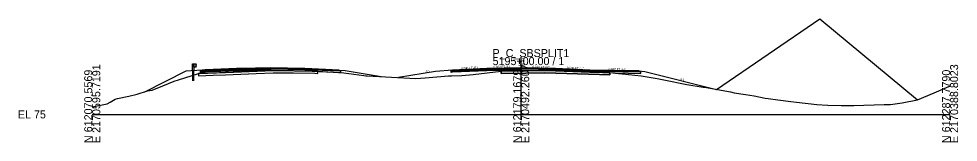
# Model space of a CAD drawing. Extents: x -26 to 1303, y -3010 to 12033.
# Drawn here: x -25.7 to 302.8, y 11990.3 to 12033.3 of the extents above; entities that cross this region are included whole.
import ezdxf

# ---------------------------------------------------------------- set-up
doc = ezdxf.new("R2010")
doc.units = 0
for name, color, linetype in [('RD_GPK_XS_Cell', 7, 'Continuous'), ('RD_PD_Final_TrvlWay', 7, 'Continuous'), ('RD_Sketch10', 7, 'Continuous'), ('RD_XS_Base', 7, 'Continuous'), ('RD_XS_ExGround', 7, 'Continuous'), ('RD_XS_ExPaveRet', 7, 'Continuous'), ('RD_XS_GR', 7, 'Continuous'), ('RD_XS_Greenside', 7, 'Continuous'), ('RD_XS_Pave', 7, 'Continuous'), ('RD_XS_PaveOvlay_CP', 7, 'Continuous'), ('RD_XS_TieSlope', 7, 'Continuous'), ('RD_XS_TX_Elev_EX', 7, 'Continuous'), ('RD_XS_TX_Elev_PR', 7, 'Continuous'), ('RD_XS_TX_Slope', 7, 'Continuous')]:
    doc.layers.add(name, color=color, linetype=linetype)

msp = doc.modelspace()

# ---------------------------------------------------------------- linework, layer by layer
at = {"layer": 'RD_GPK_XS_Cell'}
for p, q in [((150, 12000), (150, 12020)), ((0, 12000), (150, 12000)), ((150, 12000), (300, 12000))]:
    msp.add_line(p, q, dxfattribs=at)
at = {"layer": 'RD_PD_Final_TrvlWay'}
msp.add_lwpolyline([(35.54, 12011.66), (35.54, 12015.26), (35.04, 12015.22), (35.04, 12011.66)], dxfattribs=at)
at = {"layer": 'RD_Sketch10'}
msp.add_lwpolyline([(218.34, 12008.73), (254.46, 12033.35), (288.57, 12005.04)], dxfattribs=at)
at = {"layer": 'RD_XS_Base'}
for p, q in [((37.89, 12014.7), (37.89, 12015.15)), ((37.89, 12015.15), (37.94, 12015.15)), ((37.89, 12014.65), (37.89, 12014.7)), ((37.94, 12014.65), (37.89, 12014.65)), ((37.94, 12015.15), (38.39, 12015.17)), ((38.39, 12014.67), (37.94, 12014.65)), ((38.39, 12015.17), (39.51, 12015.22)), ((39.51, 12014.72), (38.39, 12014.67)), ((39.51, 12015.22), (50.39, 12015.65)), ((50.39, 12015.15), (39.51, 12014.72)), ((50.39, 12015.65), (51.68, 12015.68)), ((51.68, 12015.18), (50.39, 12015.15)), ((51.68, 12015.68), (62.39, 12015.89)), ((62.39, 12015.39), (51.68, 12015.18)), ((62.39, 12015.91), (62.39, 12016.05)), ((62.39, 12016.05), (62.39, 12015.47)), ((62.39, 12015.89), (62.39, 12016.05)), ((62.39, 12016.05), (62.39, 12015.39)), ((62.39, 12015.89), (62.39, 12015.91)), ((62.39, 12015.89), (62.39, 12015.45)), ((62.39, 12015.89), (62.39, 12015.39)), ((74.39, 12015.65), (62.39, 12015.89)), ((62.39, 12015.89), (62.39, 12015.89)), ((62.39, 12015.47), (62.39, 12015.39)), ((62.39, 12015.45), (62.39, 12015.39)), ((62.39, 12015.39), (62.39, 12015.39)), ((62.39, 12015.39), (62.39, 12015.39)), ((62.39, 12015.39), (74.39, 12015.15)), ((86.39, 12015.17), (74.39, 12015.65)), ((74.39, 12015.15), (86.89, 12014.65)), ((76.39, 12015.57), (76.39, 12015.57)), ((76.39, 12015.07), (76.39, 12015.07)), ((86.89, 12015.15), (86.39, 12015.17)), ((86.39, 12015.17), (86.39, 12015.17)), ((86.89, 12014.65), (86.89, 12015.15)), ((86.89, 12015.15), (86.89, 12015.15)), ((86.89, 12014.65), (86.89, 12014.65)), ((86.89, 12014.65), (86.89, 12014.65)), ((125.5, 12015.16), (126, 12015.18)), ((125.5, 12014.66), (125.5, 12015.16)), ((125.5, 12015.16), (125.5, 12015.16)), ((126, 12014.68), (125.5, 12014.66)), ((125.5, 12014.66), (125.5, 12014.66)), ((125.5, 12014.66), (125.5, 12014.66)), ((126, 12015.18), (138, 12015.66)), ((126, 12015.18), (126, 12015.18)), ((138, 12015.16), (126, 12014.68)), ((126, 12014.68), (126, 12014.68)), ((136, 12015.58), (136, 12015.58)), ((136, 12015.08), (136, 12015.08)), ((138, 12015.66), (150, 12015.9)), ((150, 12015.4), (138, 12015.16)), ((150, 12015.9), (150, 12016.06)), ((150, 12016.06), (150, 12015.4)), ((150, 12015.9), (150, 12015.9)), ((162, 12015.66), (150, 12015.9)), ((150, 12015.9), (150, 12015.9)), ((150, 12015.9), (150, 12015.4)), ((150, 12015.4), (150, 12015.4)), ((150, 12015.4), (162, 12015.16)), ((150, 12015.4), (150, 12015.4)), ((174, 12015.18), (162, 12015.66)), ((162, 12015.66), (162, 12015.66)), ((162, 12015.16), (162, 12015.16)), ((162, 12015.16), (174, 12014.68)), ((191.3, 12014.83), (174, 12015.18)), ((174, 12015.18), (174, 12015.18)), ((174, 12014.68), (174, 12014.68)), ((174, 12014.68), (191.8, 12014.32)), ((191.8, 12014.82), (191.3, 12014.83)), ((191.3, 12014.83), (191.3, 12014.83)), ((191.8, 12014.32), (191.8, 12014.82)), ((191.8, 12014.82), (191.8, 12014.82)), ((191.8, 12014.32), (191.8, 12014.32)), ((191.8, 12014.32), (191.8, 12014.32))]:
    msp.add_line(p, q, dxfattribs=at)
at = {"layer": 'RD_XS_ExGround'}
msp.add_lwpolyline([(0, 12002.63), (5.24, 12003.64), (6.25, 12004.22), (8.04, 12005.31), (8.83, 12005.56), (12.76, 12006.37), (15.65, 12007.1), (19.31, 12008.2), (20.9, 12008.51), (24.64, 12009.97), (28.59, 12011.6), (30.14, 12012.03), (37.21, 12014.22), (46.61, 12014.61), (63.31, 12015.31), (77.83, 12015.09), (78.86, 12015.07), (80.2, 12014.99), (80.55, 12014.97), (87.94, 12014.49), (95.02, 12013.58), (95.67, 12013.5), (96.15, 12013.51), (111.02, 12012.63), (113.17, 12012.52), (116.38, 12012.78), (124.55, 12013.47), (125.68, 12013.49), (129.27, 12013.54), (133.26, 12013.96), (143.03, 12015.03), (151.68, 12015.17), (158.3, 12015.28), (177.44, 12014.69), (180.98, 12014.58), (184.01, 12014.26), (185.29, 12014.12), (191.93, 12013.5), (196.13, 12012.73), (196.83, 12012.66), (198.15, 12012.38), (199.85, 12012.04), (207.92, 12010.42), (213.68, 12009.54), (214.13, 12009.46), (223.16, 12007.88), (224.43, 12007.55), (228.49, 12006.91), (231.44, 12006.45), (235.32, 12005.71), (236.37, 12005.49), (239.77, 12005.07), (244.26, 12004.49), (246.29, 12004.3), (253.42, 12003.51), (257.23, 12003.27), (261.91, 12003.15), (266.31, 12003.06), (276.97, 12003.43), (279.11, 12003.49), (283.23, 12004.09), (288.57, 12005.04), (294.39, 12007.47), (299.56, 12009.7), (300, 12009.88)], dxfattribs=at)
at = {"layer": 'RD_XS_ExPaveRet'}
for points in [[(78.86, 12015.07), (78.86, 12015.07), (77.83, 12015.09), (70.41, 12015.2), (63.31, 12015.31), (57.38, 12015.06), (46.61, 12014.61), (42.28, 12014.43), (37.21, 12014.22), (37.21, 12013.97), (37.21, 12013.47), (42.28, 12013.68), (46.61, 12013.86), (57.38, 12014.31), (63.31, 12014.56), (70.41, 12014.45), (77.83, 12014.34), (78.86, 12014.32), (78.86, 12014.32), (78.86, 12014.32), (78.86, 12014.32), (78.86, 12014.69), (78.86, 12015.07), (78.86, 12015.07), (78.86, 12015.07)], [(78.86, 12015.07), (78.86, 12015.07), (77.83, 12015.09), (70.41, 12015.2), (63.31, 12015.31), (57.38, 12015.06), (46.61, 12014.61), (42.28, 12014.43), (37.21, 12014.22), (37.21, 12013.97), (37.21, 12013.47), (42.28, 12013.68), (46.61, 12013.86), (57.38, 12014.31), (63.31, 12014.56), (70.41, 12014.45), (77.83, 12014.34), (78.86, 12014.32), (78.86, 12014.32), (78.86, 12014.32), (78.86, 12014.69), (78.86, 12015.07), (78.86, 12015.07)], [(180.99, 12014.58), (180.99, 12013.83), (180.99, 12013.83), (180.98, 12013.83), (180.98, 12013.83), (177.44, 12013.94), (177.44, 12013.94), (158.3, 12014.53), (158.3, 12014.53), (151.68, 12014.42), (151.68, 12014.42), (143.03, 12014.28), (143.03, 12014.28), (143.03, 12015.03), (151.68, 12015.17), (151.68, 12015.17), (158.3, 12015.28), (158.3, 12015.28), (177.44, 12014.69), (177.44, 12014.69), (180.98, 12014.58), (180.98, 12014.58), (180.99, 12014.58)], [(180.98, 12014.58), (177.44, 12014.69), (158.3, 12015.28), (151.68, 12015.17), (143.03, 12015.03), (143.03, 12014.28), (151.68, 12014.42), (158.3, 12014.53), (177.44, 12013.94), (180.98, 12013.83), (180.99, 12013.83), (180.99, 12014.58), (180.98, 12014.58)]]:
    msp.add_lwpolyline(points, dxfattribs=at)
at = {"layer": 'RD_XS_GR'}
for p, q in [((35.04, 12015.22), (35.04, 12017.66)), ((35.04, 12017.66), (35.29, 12017.66)), ((35.54, 12015.26), (35.04, 12015.22)), ((35.29, 12017.66), (35.54, 12017.66)), ((35.54, 12017.66), (35.54, 12015.26)), ((35.54, 12016.49), (35.54, 12017.66)), ((35.54, 12017.66), (36.21, 12017.66)), ((36.21, 12016.49), (35.54, 12016.49)), ((36.21, 12017.66), (36.21, 12016.49)), ((36.46, 12017.39), (36.21, 12017.66)), ((36.21, 12017.66), (36.21, 12016.59)), ((36.21, 12017.07), (36.24, 12017.1)), ((36.46, 12016.81), (36.21, 12017.07)), ((36.21, 12016.59), (36.21, 12016.49)), ((36.21, 12016.49), (36.24, 12016.52)), ((36.24, 12017.1), (36.48, 12017.37)), ((36.24, 12016.52), (36.48, 12016.78)), ((36.48, 12017.37), (36.46, 12017.39)), ((36.48, 12016.78), (36.46, 12016.81))]:
    msp.add_line(p, q, dxfattribs=at)
at = {"layer": 'RD_XS_Greenside'}
for p, q in [((32.73, 12015.04), (18.26, 12007.8)), ((88.39, 12015.33), (101.01, 12013.22)), ((120, 12015.01), (107.1, 12012.86)), ((193.3, 12014.99), (218.34, 12008.73))]:
    msp.add_line(p, q, dxfattribs=at)
at = {"layer": 'RD_XS_Pave'}
for p, q in [((39.51, 12015.53), (38.39, 12015.49)), ((38.39, 12015.49), (38.39, 12015.35)), ((39.51, 12015.38), (38.39, 12015.33)), ((38.39, 12015.33), (39.51, 12015.38)), ((38.39, 12015.35), (38.39, 12015.33)), ((38.39, 12015.33), (38.39, 12015.19)), ((38.39, 12015.17), (39.51, 12015.22)), ((38.39, 12015.19), (38.39, 12015.17)), ((50.39, 12015.97), (39.51, 12015.53)), ((50.39, 12015.81), (39.51, 12015.38)), ((39.51, 12015.38), (50.39, 12015.81)), ((39.51, 12015.22), (50.39, 12015.65)), ((51.68, 12015.99), (50.39, 12015.97)), ((51.68, 12015.84), (50.39, 12015.81)), ((50.39, 12015.81), (51.68, 12015.84)), ((50.39, 12015.65), (51.68, 12015.68)), ((62.39, 12016.21), (51.68, 12015.99)), ((62.39, 12016.05), (51.68, 12015.84)), ((51.68, 12015.84), (62.39, 12016.05)), ((51.68, 12015.68), (62.39, 12015.89)), ((74.39, 12015.97), (62.39, 12016.21)), ((62.39, 12015.91), (62.39, 12016.05)), ((62.39, 12016.05), (62.39, 12015.91)), ((62.39, 12015.89), (62.39, 12016.05)), ((62.39, 12016.05), (74.39, 12015.81)), ((74.39, 12015.81), (62.39, 12016.05)), ((62.39, 12016.05), (62.39, 12015.89)), ((62.39, 12015.89), (62.39, 12015.91)), ((62.39, 12015.91), (62.39, 12015.89)), ((62.39, 12015.89), (62.39, 12015.89)), ((62.39, 12015.89), (62.39, 12015.89)), ((62.39, 12015.89), (74.39, 12015.65)), ((86.39, 12015.49), (74.39, 12015.97)), ((74.39, 12015.81), (86.39, 12015.33)), ((86.39, 12015.33), (74.39, 12015.81)), ((74.39, 12015.65), (86.39, 12015.17)), ((76.39, 12015.89), (76.39, 12015.89)), ((76.39, 12015.73), (76.39, 12015.73)), ((76.39, 12015.73), (76.39, 12015.73)), ((76.39, 12015.57), (76.39, 12015.57)), ((86.39, 12015.33), (86.39, 12015.49)), ((86.39, 12015.49), (86.39, 12015.49)), ((86.39, 12015.33), (86.39, 12015.33)), ((86.39, 12015.33), (86.39, 12015.33)), ((86.39, 12015.17), (86.39, 12015.33)), ((86.39, 12015.33), (86.39, 12015.33)), ((86.39, 12015.17), (86.39, 12015.17)), ((86.39, 12015.17), (86.39, 12015.17)), ((138, 12015.97), (126, 12015.49)), ((138, 12015.82), (126, 12015.34)), ((126, 12015.34), (138, 12015.82)), ((126, 12015.18), (138, 12015.66)), ((126, 12015.49), (126, 12015.49)), ((126, 12015.49), (126, 12015.34)), ((126, 12015.34), (126, 12015.34)), ((126, 12015.34), (126, 12015.18)), ((126, 12015.34), (126, 12015.34)), ((126, 12015.34), (126, 12015.34)), ((126, 12015.18), (126, 12015.18)), ((126, 12015.18), (126, 12015.18)), ((136, 12015.89), (136, 12015.89)), ((136, 12015.74), (136, 12015.74)), ((136, 12015.74), (136, 12015.74)), ((136, 12015.58), (136, 12015.58)), ((150, 12016.21), (138, 12015.97)), ((150, 12016.06), (138, 12015.82)), ((138, 12015.82), (150, 12016.06)), ((138, 12015.66), (150, 12015.9)), ((162, 12015.97), (150, 12016.21)), ((150, 12015.9), (150, 12016.06)), ((150, 12016.06), (162, 12015.82)), ((162, 12015.82), (150, 12016.06)), ((150, 12016.06), (150, 12016.06)), ((150, 12016.06), (150, 12015.9)), ((150, 12015.9), (150, 12015.9)), ((150, 12015.9), (150, 12015.9)), ((150, 12015.9), (150, 12015.9)), ((150, 12015.9), (162, 12015.66)), ((174, 12015.49), (162, 12015.97)), ((162, 12015.97), (162, 12015.97)), ((162, 12015.82), (162, 12015.82)), ((162, 12015.82), (174, 12015.34)), ((174, 12015.34), (162, 12015.82)), ((162, 12015.82), (162, 12015.82)), ((162, 12015.66), (162, 12015.66)), ((162, 12015.66), (174, 12015.18)), ((191.3, 12015.15), (174, 12015.49)), ((174, 12015.49), (174, 12015.49)), ((174, 12015.34), (174, 12015.34)), ((174, 12015.34), (191.3, 12014.99)), ((191.3, 12014.99), (174, 12015.34)), ((174, 12015.34), (174, 12015.34)), ((174, 12015.18), (174, 12015.18)), ((174, 12015.18), (191.3, 12014.83)), ((191.3, 12014.99), (191.3, 12015.15)), ((191.3, 12015.15), (191.3, 12015.15)), ((191.3, 12014.99), (191.3, 12014.99)), ((191.3, 12014.99), (191.3, 12014.99)), ((191.3, 12014.83), (191.3, 12014.99)), ((191.3, 12014.99), (191.3, 12014.99)), ((191.3, 12014.83), (191.3, 12014.83)), ((191.3, 12014.83), (191.3, 12014.83))]:
    msp.add_line(p, q, dxfattribs=at)
at = {"layer": 'RD_XS_PaveOvlay_CP'}
for p, q in [((38.39, 12015.49), (50.39, 12015.97)), ((50.39, 12015.97), (62.39, 12016.21)), ((62.39, 12016.21), (74.39, 12015.97)), ((74.39, 12015.97), (86.39, 12015.49)), ((138, 12015.97), (126, 12015.49)), ((126, 12015.49), (126, 12015.49)), ((136, 12015.89), (136, 12015.89)), ((150, 12016.21), (138, 12015.97)), ((162, 12015.97), (150, 12016.21)), ((174, 12015.49), (162, 12015.97)), ((162, 12015.97), (162, 12015.97)), ((191.3, 12015.15), (174, 12015.49)), ((174, 12015.49), (174, 12015.49)), ((191.3, 12015.15), (191.3, 12015.15))]:
    msp.add_line(p, q, dxfattribs=at)
at = {"layer": 'RD_XS_TieSlope'}
for p, q in [((38.39, 12015.49), (32.73, 12015.04)), ((86.39, 12015.49), (88.39, 12015.33)), ((126, 12015.49), (120, 12015.01)), ((191.3, 12015.15), (193.3, 12014.99))]:
    msp.add_line(p, q, dxfattribs=at)

# ---------------------------------------------------------------- texts
at = {"layer": 'RD_GPK_XS_Cell'}
for s, p in [('P_C_SBSPLIT1', (140, 12020)), ('5195+00.00 / 1', (140, 12017.2)), ('EL 75', (-26, 11998.6))]:
    msp.add_text(s, height=2.8, dxfattribs=at).set_placement(p)
for s, p in [('N 612070.5569', (0, 11990)), ('E 2170595.7191', (2.8, 11990)), ('N 612179.1679', (150, 11990)), ('E 2170492.2607', (152.8, 11990)), ('N 612287.7790', (300, 11990)), ('E 2170388.8023', (302.8, 11990))]:
    msp.add_text(s, height=2.8, rotation=90, dxfattribs=at).set_placement(p)
at = {"layer": 'RD_XS_TX_Elev_EX'}
msp.add_text('90.14', height=0.6, rotation=90, dxfattribs=at).set_placement((149.68, 12016.82))
at = {"layer": 'RD_XS_TX_Elev_PR'}
msp.add_text('91.21', height=1, rotation=90, dxfattribs=at).set_placement((151.25, 12016.41))
at = {"layer": 'RD_XS_TX_Slope'}
for s, rotation, p in [('6:1', 9.4623, (116.7, 12014.52)), ('0.040 FT./FT.', 2.2906, (128.93, 12015.71)), ('0.020 FT./FT.', 1.1458, (140.27, 12016.19)), ('0.020 FT./FT.', 358.8542, (153.94, 12016.23)), ('0.040 FT./FT.', 357.7094, (165.94, 12015.92)), ('0.020 FT./FT.', 358.8542, (180.59, 12015.46)), ('4:1', 345.9638, (205.53, 12011.99))]:
    msp.add_text(s, height=0.75, rotation=rotation, dxfattribs=at).set_placement(p)

doc.saveas('drawing.dxf')
